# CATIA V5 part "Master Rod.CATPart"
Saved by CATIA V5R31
Part number: Master Rod
Bounding box of the stored display mesh (mm): x -55.99 to 55.99, y -51.999 to 267.322, z -35 to 35
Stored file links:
  D:\PROJECTS\Project 2021\US EDITION\CATIA V5 6R 2021\Resources\Part Files\c12_catia_v5_6r2021_prt\c12_catia_v5-6r2021 figr_12-26\Master Rod.CATPart
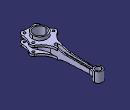
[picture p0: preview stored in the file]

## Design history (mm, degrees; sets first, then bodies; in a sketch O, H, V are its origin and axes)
Body1 (main body)
  Sketch1 on xy-plane, origin (0, 0, 0), H (1, 0, 0), V (0, 1, 0)
    arc A1 centre (0, 0) radius 31.5 from (-26.3425, 17.272) to (26.3425, 17.272) ccw
    arc A2 centre (0, 250) radius 17.5 from (14.7398, 240.5666) to (-14.7398, 240.5666) ccw
    point P1 (0, 250)
    line L1 (9, 220) -> (13, 60)
    point P2 (9, 220)
    point P3 (13, 60)
    arc A3 centre (94.6219, 62.0405) radius 81.6474 from (13, 60) to (26.3425, 17.272) ccw
    point P5 (26.3425, 17.272)
    arc A4 centre (45.4514, 220.9113) radius 36.4628 from (9, 220) to (14.7398, 240.5666) cw
    point P7 (14.7398, 240.5666)
    point P8 (-14.7398, 240.5666)
    point P9 (-9, 220)
    arc A5 centre (-45.4514, 220.9113) radius 36.4628 from (-9, 220) to (-14.7398, 240.5666) ccw
    point P11 (-13, 60)
    line L2 (-9, 220) -> (-13, 60)
    point P12 (-26.3425, 17.272)
    arc A6 centre (-94.6219, 62.0405) radius 81.6474 from (-13, 60) to (-26.3425, 17.272) cw
    radius A1 = 31.5
    radius A2 = 17.5
    distance P1 H = 250
    distance V P3 = 13
    distance P2 V = 9
    distance P1 P2 V = 30
    distance P3 P2 V = 160
    coincidence: P1 V
    tangency: A3 L1, A3 A1, A4 L1, A4 A2
    symmetry: P7 P8 V, P2 P9 V, A4 A5 V, P3 P11 V, L1 L2 V, P5 P12 V, A3 A6 V
  Pad1: profile Sketch1, direction (0, 0, 1), length 21, mirrored extent
  Sketch2 on face of Pad1, origin (0, 0, 21), H (1, 0, 0), V (0, 1, 0)
    point P1 (43, 16)
    point P2 (26, -39)
    arc A1 centre (43, 16) radius 13 from (53.3864, 8.1819) to (49.3111, 27.3653) ccw
    arc A2 centre (26, -39) radius 13 from (22.0235, -51.3769) to (38.9864, -38.4063) ccw
    reference projected line E1 (9, 220) -> (12.2872, 88.5122) from edge of Pad1
    arc A3 centre (84.2647, 90.3117) radius 72 from (49.3111, 27.3653) to (12.2872, 88.5122) cw
    point P5 (49.3111, 27.3653)
    point P6 (12.2872, 88.5122)
    arc A4 centre (110.9113, -35.118) radius 72 from (38.9864, -38.4063) to (53.3864, 8.1819) cw
    point P8 (38.9864, -38.4063)
    point P9 (53.3864, 8.1819)
    point P10 (-12.2872, 88.5122)
    point P11 (-49.3111, 27.3653)
    arc A5 centre (-84.2647, 90.3117) radius 72 from (-49.3111, 27.3653) to (-12.2872, 88.5122) ccw
    point P13 (-53.3864, 8.1819)
    arc A6 centre (-43, 16) radius 13 from (-53.3864, 8.1819) to (-49.3111, 27.3653) cw
    point P15 (-38.9864, -38.4063)
    arc A7 centre (-110.9113, -35.118) radius 72 from (-38.9864, -38.4063) to (-53.3864, 8.1819) ccw
    arc A8 centre (-26, -39) radius 13 from (-22.0235, -51.3769) to (-38.9864, -38.4063) cw
    line L1 (12.2872, 88.5122) -> (-12.2872, 88.5122)
    arc A9 centre (0, -119.9259) radius 72 from (-22.0235, -51.3769) to (22.0235, -51.3769) cw
    distance V P2 = 26
    distance P2 P1 H = 17
    distance P1 P2 V = 55
    distance P2 H = 39
    radius A1 = 13
    radius A2 = 13
    radius A3 = 72
    radius A4 = 72
    radius A9 = 72
    tangency: A3 E1, A3 A1, A4 A1, A4 A2, A9 A8, A9 A2
    symmetry: P6 P10 V, P5 P11 V, A3 A5 V, P9 P13 V, A1 A6 V, P8 P15 V, A4 A7 V, A2 A8 V
    horizontal: L1 H
  Pad2: profile Sketch2, direction (0, 0, -1), length 9
  Mirror1: of Pad2, Sketch2, about xy-plane
  Sketch3 on xy-plane, origin (0, 0, 0), H (1, 0, 0), V (0, 1, 0)
    circle A1 centre (0, 0) radius 31.5
    reference projected arc E1 centre (0, 0) radius 31.5 from (-26.3425, 17.272) to (26.3425, 17.272) ccw from edge of Pad2
    tangency: A1 E1
  Pad3: profile Sketch3, direction (0, 0, 1), length 35, mirrored extent
  Sketch4 on xy-plane, origin (0, 0, 0), H (1, 0, 0), V (0, 1, 0)
    circle A1 centre (0, 0) radius 26
    circle A2 centre (43, 16) radius 5
    circle A3 centre (26, -39) radius 5
    reference projected arc E1 centre (43, 16) radius 13 from (53.3864, 8.1819) to (49.3111, 27.3653) ccw from edge of Pad2
    reference projected arc E2 centre (26, -39) radius 13 from (22.0235, -51.3769) to (38.9864, -38.4063) ccw from edge of Pad2
    circle A4 centre (-26, -39) radius 5
    circle A5 centre (-43, 16) radius 5
    radius A1 = 26
    radius A3 = 5
    radius A2 = 5
    concentricity: A2 E1, A3 E2
    symmetry: A3 A4 V, A2 A5 V
  Pocket1: profile Sketch4, direction (0, 0, -1), length 35, mirrored extent
  Sketch5 on yz-plane, origin (0, 0, 0), H (0, 1, 0), V (0, 0, 1)
    line L1 (123.0834, 12) -> (250, 9)
    point P1 (123.0834, 12)
    point P2 (250, 9)
    arc A1 centre (124.9266, 89.9782) radius 78 from (88.5122, 21) to (123.0834, 12) ccw
    line L2 (88.5122, 21) -> (88.5122, 33.8539)
    line L3 (88.5122, 33.8539) -> (280.7471, 33.8539)
    line L4 (280.7471, 33.8539) -> (280.7471, 8.2732)
    point P8 (280.7471, 8.2732)
    line L5 (280.7471, 8.2732) -> (250, 9)
    distance P1 H = 12
    distance H P2 = 9
    distance V P2 = 250
    radius A1 = 78
    tangency: A1 L1, L5 A1
    vertical: L2 V, L4 V
    horizontal: L3 H
    coincidence: P8 L1
  Pocket2: profile Sketch5, direction (-1, 0, 0), length 35, mirrored extent
  Mirror2: of Pocket2, Sketch5, about xy-plane
  Sketch6 on xy-plane, origin (0, 0, 0), H (1, 0, 0), V (0, 1, 0)
    circle A1 centre (0, 250) radius 17.5
    point P1 (0, 250)
    reference projected arc E1 centre (0, 250) radius 17.5 from (17.5, 250) to (-17.5, 250) ccw from edge of Mirror2
    reference projected arc E2 centre (0, 250) radius 17.5 from (17.5, 250) to (-17.5, 250) ccw from edge of Mirror2
    coincidence: P1 V
    concentricity: E1 A1
    tangency: E2 A1
  Pad4: profile Sketch6, direction (0, 0, 1), length 21, mirrored extent
  Sketch7 on xy-plane, origin (0, 0, 0), H (1, 0, 0), V (0, 1, 0)
    circle A1 centre (0, 250) radius 12
    point P1 (0, 250)
    reference projected circle E1 centre (0, 250) radius 17.5 from edge of Pad4
    radius A1 = 12
    coincidence: P1 V
    concentricity: A1 E1
  Pocket3: profile Sketch7, direction (0, 0, -1), length 21, mirrored extent
  Sketch8 on xy-plane, origin (0, 0, 0), H (1, 0, 0), V (0, 1, 0)
    construction line L1 (0, 70) -> (0, 220)
    point P1 (0, 70)
    point P2 (0, 220)
    line L2 (-6, 70) -> (-6, 220)
    line L3 (6, 220) -> (6, 70)
    arc A1 centre (0, 220) radius 6 from (-6, 220) to (6, 220) cw
    arc A2 centre (0, 70) radius 6 from (6, 70) to (-6, 70) cw
    point P7 (0, 250)
    reference projected circle E1 centre (0, 250) radius 12 from edge of Pocket3
    length L1 = 150
    distance P7 P2 = 30
    radius A1 = 6
    coincidence: P1 V, P7 L1
    vertical: L1 V
    tangency: A1 L2, A2 L2, A1 L3, A2 L3
    parallelism: L1 L2
    concentricity: P7 E1
  Pocket4: profile Sketch8, direction (0, 0, 1), through (limit type 6), opposite side length -2.5
  Mirror3: of Pocket4, Sketch8, about xy-plane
